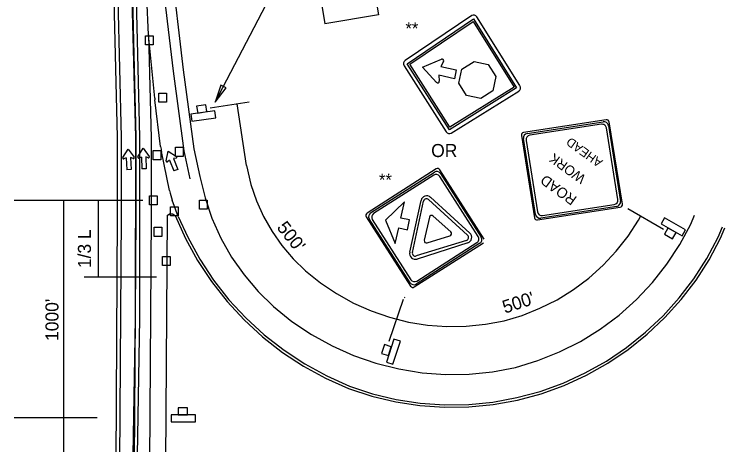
# Model space of a CAD drawing. Extents: x 612.5 to 619.9, y 600.8 to 610.9.
# Drawn here: x 615.256 to 618.528, y 604.113 to 606.093 of the extents above; entities that cross this region are included whole.
import ezdxf

# ---------------------------------------------------------------- set-up
doc = ezdxf.new("R2010")
doc.units = 0
for name, color, linetype in [('DETL-DIMS', 7, 'Continuous'), ('DETL-LINE', 7, 'Continuous'), ('DETL-NOTE', 7, 'Continuous'), ('USER-BORD', 7, 'Continuous')]:
    doc.layers.add(name, color=color, linetype=linetype)

# ---------------------------------------------------------------- blocks, each defined once
blk = doc.blocks.new('SIGN14')
at = {"layer": 'USER-BORD'}
for points in [[(-0.0134, 0.0182), (0.011, 0.0189), (0.011, 0.0371), (-0.0134, 0.0371)], [(-0.0314, 0.0182), (-0.0314, 0), (0.032, 0), (0.032, 0.0182)]]:
    blk.add_lwpolyline(points, close=True, dxfattribs=at)

msp = doc.modelspace()

# ---------------------------------------------------------------- linework, layer by layer
at = {"layer": 'DETL-DIMS'}
for p, q in [((616.1815, 605.6878), (616.5998, 606.491)), ((616.158, 605.6621), (616.3376, 605.6893)), ((616.3254, 605.3974), (616.2824, 605.6809)), ((615.8484, 605.2358), (615.2559, 605.2358)), ((615.485, 602.8086), (615.485, 605.2358)), ((615.6422, 605.2358), (615.6422, 604.8833)), ((618.2463, 605.1021), (618.0817, 605.1972)), ((615.9113, 604.8833), (615.5777, 604.8833)), ((616.9829, 604.5886), (617.0491, 604.7818)), ((615.6377, 604.2368), (615.2559, 604.2368))]:
    msp.add_line(p, q, dxfattribs=at)
msp.add_lwpolyline([(616.2314, 605.7535), (616.2074, 605.7661), (616.1815, 605.6878)], close=True, dxfattribs=at)
msp.add_lwpolyline([(616.3254, 605.3974), (616.3462, 605.3101), (616.3717, 605.2351), (616.4044, 605.1627), (616.4435, 605.0936), (616.489, 605.0284), (616.54, 604.968), (616.5966, 604.9129), (616.6656, 604.8574), (616.7397, 604.8076), (616.818, 604.7643), (616.8997, 604.728), (616.9843, 604.6989), (617.0712, 604.6771), (617.1593, 604.663), (617.2485, 604.6564), (617.3379, 604.6576), (617.4269, 604.6666), (617.5128, 604.6827), (617.595, 604.7075), (617.6771, 604.7404), (617.7558, 604.78), (617.8308, 604.8266), (617.9016, 604.8795), (617.9674, 604.9383), (618.0279, 605.0026), (618.0826, 605.072), (618.1311, 605.1459), (618.1404, 605.1632)], dxfattribs=at)
at = {"layer": 'DETL-LINE'}
for p, q in [((616.8941, 606.327), (616.933, 606.0896)), ((616.6468, 606.2864), (616.6857, 606.049)), ((615.8748, 605.9976), (615.8657, 606.181)), ((616.933, 606.0896), (616.6857, 606.049)), ((615.9032, 605.7068), (615.8748, 605.9976)), ((617.1358, 605.8489), (617.2232, 605.886)), ((617.2325, 605.876), (617.221, 605.8517)), ((617.3176, 605.8401), (617.374, 605.8761)), ((617.374, 605.8761), (617.4382, 605.862)), ((617.2011, 605.7795), (617.1358, 605.8489)), ((617.221, 605.8517), (617.2918, 605.8374)), ((617.2918, 605.8374), (617.2827, 605.7958)), ((617.3033, 605.7754), (617.3176, 605.8401)), ((617.4382, 605.862), (617.4743, 605.806)), ((617.2828, 605.7962), (617.2118, 605.8119)), ((617.2118, 605.8119), (617.2129, 605.7852)), ((617.4743, 605.806), (617.4603, 605.7404)), ((617.2011, 605.7795), (617.2011, 605.7795)), ((617.3394, 605.7194), (617.3033, 605.7754)), ((617.4603, 605.7404), (617.4041, 605.7052)), ((617.4041, 605.7052), (617.3394, 605.7194)), ((615.9303, 605.4846), (615.904, 605.6997)), ((617.9825, 605.6072), (617.6016, 605.5486)), ((617.6182, 605.5444), (617.9684, 605.5982)), ((617.9599, 605.5866), (617.6299, 605.5358)), ((617.9919, 605.5812), (618.0476, 605.2322)), ((618.0566, 605.2186), (617.9962, 605.5973)), ((618.0359, 605.2407), (617.9834, 605.5696)), ((617.5917, 605.5351), (617.6522, 605.1564)), ((617.6569, 605.172), (617.6011, 605.5211)), ((617.6129, 605.5126), (617.6655, 605.1837)), ((615.756, 605.4338), (615.7804, 605.4728)), ((615.7804, 605.4728), (615.8078, 605.4359)), ((615.8256, 605.437), (615.85, 605.476)), ((615.85, 605.476), (615.8774, 605.4391)), ((615.9711, 605.2814), (615.9342, 605.4607)), ((615.9551, 605.4182), (615.9646, 605.4632)), ((615.9646, 605.4632), (616.003, 605.4379)), ((615.772, 605.4321), (615.7607, 605.4278)), ((615.772, 605.4321), (615.7746, 605.3778)), ((615.8038, 605.4297), (615.792, 605.4331)), ((615.792, 605.4331), (615.7944, 605.3784)), ((615.8417, 605.4353), (615.8302, 605.431)), ((615.8417, 605.4353), (615.8442, 605.381)), ((615.8734, 605.433), (615.8616, 605.4362)), ((615.8616, 605.4362), (615.8638, 605.3817)), ((615.9707, 605.4221), (615.9614, 605.4142)), ((615.9707, 605.4221), (615.9916, 605.372)), ((616.0014, 605.4308), (615.9891, 605.4297)), ((615.9891, 605.4297), (616.0098, 605.3794)), ((615.7944, 605.3784), (615.7746, 605.3778)), ((615.8638, 605.3817), (615.8442, 605.381)), ((616.0098, 605.3794), (615.9916, 605.372)), ((617.1996, 605.381), (616.8809, 605.1775)), ((617.4198, 605.058), (617.2159, 605.3775)), ((616.8971, 605.1794), (617.1908, 605.367)), ((617.1877, 605.3531), (616.911, 605.1764)), ((617.3923, 605.0702), (617.2154, 605.347)), ((617.2185, 605.3609), (617.4061, 605.0672)), ((617.3542, 605.0861), (617.1732, 605.2507)), ((616.0114, 605.1627), (615.9835, 605.2381)), ((616.966, 605.1456), (617.0533, 605.23)), ((617.077, 604.9978), (617.1296, 605.2368)), ((617.0893, 604.9974), (617.1414, 605.2334)), ((617.1643, 605.2406), (617.3439, 605.0763)), ((617.6889, 605.1666), (618.0189, 605.2175)), ((617.6655, 605.1837), (617.6655, 605.1837)), ((617.6658, 605.1465), (618.0468, 605.2051)), ((618.0306, 605.209), (617.6803, 605.1551)), ((615.7303, 605.1667), (615.713, 602.4075)), ((615.7481, 605.1667), (615.7308, 602.4075)), ((615.8154, 605.1666), (615.7981, 602.4075)), ((615.8862, 605.1665), (615.8689, 602.4074)), ((615.9597, 605.1665), (615.9424, 602.4073)), ((616.8774, 605.1613), (617.0814, 604.8418)), ((617.0786, 604.8579), (616.891, 605.1516)), ((616.9048, 605.1485), (617.0816, 604.8718)), ((616.911, 605.1764), (616.9109, 605.1763)), ((616.966, 605.1456), (617.0108, 605.0382)), ((617.1677, 605.1591), (617.1444, 605.0534)), ((617.1677, 605.1592), (617.1677, 605.1591)), ((617.2661, 605.0915), (617.1849, 605.1646)), ((616.9838, 605.1078), (616.9838, 605.1078)), ((617.3386, 605.0528), (617.107, 604.9811)), ((617.1577, 605.0412), (617.2622, 605.0738)), ((617.0976, 604.8383), (617.4163, 605.0419)), ((617.4, 605.0394), (617.1063, 604.8518)), ((617.1094, 604.8657), (617.3862, 605.0425)), ((617.3444, 605.0414), (617.1108, 604.967))]:
    msp.add_line(p, q, dxfattribs=at)
for points in [[(615.743, 602.4107), (615.7794, 602.9085), (615.8185, 603.7952), (615.8337, 604.693), (615.8344, 605.528), (615.8187, 606.1632), (615.7799, 607.0362)], [(615.6811, 606.9197), (615.715, 606.1596), (615.7306, 605.5268), (615.7303, 605.1667)], [(615.6989, 606.9205), (615.7327, 606.1602), (615.7484, 605.5269), (615.7481, 605.1667)], [(615.7641, 606.9234), (615.798, 606.1625), (615.8137, 605.5277), (615.813, 604.6932), (615.7977, 603.7958), (615.7587, 602.9098), (615.7222, 602.4111)], [(615.7662, 606.9235), (615.8, 606.1626), (615.8157, 605.5277), (615.8154, 605.1666)], [(615.8847, 606.94), (615.9293, 606.3182), (615.9874, 605.8308), (616.0364, 605.4649), (616.065, 605.3359)], [(615.932, 606.9434), (615.9765, 606.3227), (616.0345, 605.8368), (616.0832, 605.4732), (616.1113, 605.3462)], [(615.932, 606.9434), (615.9765, 606.3227), (616.0345, 605.8368), (616.0832, 605.4732), (616.1113, 605.3462)], [(615.932, 606.9434), (615.9765, 606.3227), (616.0345, 605.8368), (616.0832, 605.4732), (616.1113, 605.3462)], [(615.932, 606.9434), (615.9765, 606.3227), (616.0345, 605.8368), (616.0832, 605.4732), (616.1113, 605.3462)], [(617.3626, 606.0866), (617.0562, 605.8797)], [(617.0662, 605.8652), (617.3716, 606.0709)], [(617.3716, 606.0709), (617.5696, 605.7546)], [(617.5842, 605.7646), (617.386, 606.0805)], [(617.0772, 605.8628), (617.3693, 606.0591)], [(617.3693, 606.0591), (617.5583, 605.7571)], [(615.8748, 605.9976), (615.8865, 605.5231), (615.8862, 605.1665)], [(617.2603, 605.5606), (617.0662, 605.8652)], [(617.0513, 605.8556), (617.2444, 605.5518)], [(617.2622, 605.573), (617.0772, 605.8628)], [(617.5696, 605.7546), (617.2603, 605.5606)], [(617.5583, 605.7571), (617.2622, 605.573)], [(617.2685, 605.5457), (617.5791, 605.7393)], [(616.1113, 605.3462), (616.1345, 605.249), (616.1667, 605.1542), (616.2078, 605.063), (616.257, 604.9761), (616.3143, 604.894), (616.3788, 604.8178), (616.4504, 604.748), (616.5349, 604.68), (616.625, 604.6195), (616.72, 604.567), (616.819, 604.523), (616.9215, 604.4877), (617.0269, 604.4612), (617.1338, 604.4441), (617.2419, 604.4362), (617.3504, 604.4376), (617.4583, 604.4485), (617.565, 604.4686), (617.6678, 604.4996), (617.7677, 604.5395), (617.8636, 604.5879), (617.955, 604.6446), (618.041, 604.7089), (618.1212, 604.7805), (618.1949, 604.8588), (618.2614, 604.9432), (618.3204, 605.0331), (618.3712, 605.1277), (618.3891, 605.1692)], [(615.9597, 605.1665), (615.9708, 605.1752), (615.985, 605.1755), (615.9964, 605.1671), (616.0441, 605.0615), (616.1001, 604.96), (616.1642, 604.8634), (616.2358, 604.7723), (616.3146, 604.6873), (616.4, 604.6089), (616.4914, 604.5377), (616.5882, 604.4741), (616.6899, 604.4185), (616.7958, 604.3713), (616.903, 604.336), (617.0128, 604.3097), (617.1244, 604.2927), (617.237, 604.2849), (617.3499, 604.2865), (617.4622, 604.2975), (617.5733, 604.3177), (617.6823, 604.3471), (617.7885, 604.3854), (617.8911, 604.4323), (617.9896, 604.4877), (618.083, 604.5509), (618.171, 604.6217), (618.2527, 604.6979), (618.3277, 604.7807), (618.3956, 604.8694), (618.4558, 604.9636), (618.5079, 605.0624), (618.5282, 605.1102)], [(616.0114, 605.1627), (616.0547, 605.0668), (616.1103, 604.9662), (616.1738, 604.8704), (616.2449, 604.78), (616.323, 604.6957), (616.4076, 604.618), (616.4983, 604.5473), (616.5944, 604.4842), (616.6952, 604.4291), (616.8001, 604.3823), (616.9063, 604.3474), (617.0151, 604.3214), (617.1257, 604.3045), (617.2373, 604.2968), (617.3492, 604.2984), (617.4606, 604.3093), (617.5707, 604.3293), (617.6787, 604.3584), (617.784, 604.3964), (617.8858, 604.4429), (617.9833, 604.4978), (618.076, 604.5605), (618.1632, 604.6307), (618.2442, 604.7063), (618.3186, 604.7883), (618.3859, 604.8762), (618.4455, 604.9695), (618.4971, 605.0675), (618.5172, 605.1148)], [(617.0524, 604.7914), (617.0551, 604.7904)]]:
    msp.add_lwpolyline(points, dxfattribs=at)
for points in [[(615.8965, 605.9518), (615.861, 605.9518), (615.861, 605.994), (615.8965, 605.994)], [(615.9575, 605.6878), (615.922, 605.6878), (615.922, 605.73), (615.9575, 605.73)], [(616.0344, 605.4384), (615.999, 605.4384), (615.999, 605.4806), (616.0344, 605.4806)], [(615.931, 605.4238), (615.8955, 605.4238), (615.8955, 605.466), (615.931, 605.466)], [(615.9138, 605.2156), (615.8783, 605.2156), (615.8783, 605.2578), (615.9138, 605.2578)], [(616.1445, 605.1957), (616.109, 605.1957), (616.109, 605.2379), (616.1445, 605.2379)], [(617.0666, 605.1017), (617.0765, 605.1465), (617.0368, 605.1553), (617.0533, 605.23), (616.966, 605.1456), (617.0108, 605.0382), (617.0267, 605.1105)], [(616.0106, 605.1652), (615.9751, 605.1652), (615.9751, 605.2074), (616.0106, 605.2074)], [(615.9363, 605.071), (615.9008, 605.071), (615.9008, 605.1132), (615.9363, 605.1132)], [(615.9748, 604.937), (615.9393, 604.937), (615.9393, 604.9792), (615.9748, 604.9792)]]:
    msp.add_lwpolyline(points, close=True, dxfattribs=at)
for centre, radius, start, end in [((616.1985, 605.7357), 0.2966, 185.5888, 186.9597), ((616.2247, 605.5205), 0.2966, 186.9597, 191.6264), ((615.7594, 605.4316), 0.00391, 148.1267, 290.387), ((615.8048, 605.4335), 0.00391, 254.3871, 36.6474), ((615.829, 605.4348), 0.00391, 148.1267, 290.387), ((615.8744, 605.4367), 0.00391, 254.3871, 36.6474), ((615.9589, 605.4173), 0.00391, 168.1267, 310.387), ((616.001, 605.4346), 0.00391, 274.3871, 56.6474), ((616.2616, 605.3412), 0.2966, 191.6264, 200.3362)]:
    msp.add_arc(centre, radius, start, end, dxfattribs=at)
for centre, major_axis, ratio, start_param, end_param in [((617.3717, 606.0714), (-0.0171, 0.0038), 0.999922, 3.926991, 5.497787), ((617.0662, 605.8652), (-0.0171, 0.0038), 0.999922, 5.54537, 7.042948), ((617.2264, 605.8791), (-0.00713, 0.00157), 0.999922, 2.884299, 5.327729), ((617.2061, 605.7846), (-0.00713, 0.00157), 0.999922, 0.964393, 3.407823), ((617.57, 605.7546), (0.0171, -0.0038), 0.999922, 5.421015, 7.068583), ((617.9844, 605.5955), (-0.011, 0.0047), 0.993733, 3.70184, 5.272637), ((617.9631, 605.5665), (-0.0188, 0.0081), 0.993733, 3.70184, 5.272637), ((617.9716, 605.5781), (-0.0188, 0.0081), 0.993733, 3.70184, 5.272637), ((617.2597, 605.5612), (-0.0171, 0.0038), 0.999922, 0.785398, 2.312744), ((617.6035, 605.5369), (-0.011, 0.0047), 0.993733, 5.272637, 6.843433), ((617.6214, 605.5242), (-0.0188, 0.0081), 0.993733, 5.272637, 6.843433), ((617.6331, 605.5157), (-0.0188, 0.0081), 0.993733, 5.272637, 6.843433), ((617.206, 605.3711), (-0.0115, 0.0025), 0.999922, 3.926991, 5.497787), ((617.1985, 605.3361), (-0.0196, 0.0043), 0.999922, 3.926991, 5.497787), ((617.2016, 605.35), (-0.0196, 0.0043), 0.999922, 3.926991, 5.497787), ((617.1555, 605.2311), (-0.0258, 0.0057), 0.999922, 4.191063, 6.283185), ((617.1549, 605.2304), (-0.0136, 0.003), 0.999922, 4.18832, 6.283185), ((618.0157, 605.2376), (-0.0188, 0.0081), 0.993733, 2.131044, 3.70184), ((618.0274, 605.2291), (-0.0188, 0.0081), 0.993733, 2.131044, 3.70184), ((618.0448, 605.2168), (-0.011, 0.0047), 0.993733, 2.131044, 3.70184), ((616.9079, 605.1624), (-0.0196, 0.0043), 0.999922, 5.497787, 7.068583), ((617.6856, 605.1868), (-0.0188, 0.0081), 0.993733, 0.560248, 2.131044), ((616.8873, 605.1676), (-0.0115, 0.0025), 0.999922, 5.497787, 7.068583), ((616.9218, 605.1593), (-0.0196, 0.0043), 0.999922, 5.497787, 7.068583), ((617.178, 605.1569), (-0.0102, 0.0023), 0.999922, 4.195513, 6.283185), ((617.6639, 605.1582), (-0.011, 0.0047), 0.993733, 0.560248, 2.131044), ((617.6771, 605.1752), (-0.0188, 0.0081), 0.993733, 0.560248, 2.131044), ((617.2591, 605.0837), (-0.0102, 0.0023), 0.999922, 2.089942, 4.195513), ((617.3364, 605.0665), (-0.0258, 0.0057), 0.999922, 2.096108, 4.191063), ((617.1546, 605.0512), (-0.0102, 0.0023), 0.999922, 0, 2.089942), ((617.3346, 605.066), (-0.0136, 0.003), 0.999922, 2.087614, 4.18832), ((617.3753, 605.0594), (-0.0196, 0.0043), 0.999922, 2.356194, 3.926991), ((617.3892, 605.0563), (-0.0196, 0.0043), 0.999922, 2.356194, 3.926991), ((617.1028, 604.9921), (-0.0258, 0.0057), 0.999922, 0, 2.096108), ((617.1029, 604.9944), (-0.0136, 0.003), 0.999922, 0, 2.087614), ((617.0955, 604.8687), (-0.0196, 0.0043), 0.999922, 0.785398, 2.356194), ((617.0985, 604.8826), (-0.0196, 0.0043), 0.999922, 0.785398, 2.356194), ((617.0913, 604.8482), (-0.0115, 0.0025), 0.999922, 0.785398, 2.356194)]:
    msp.add_ellipse(centre, major_axis=major_axis, ratio=ratio, start_param=start_param, end_param=end_param, dxfattribs=at)

# ---------------------------------------------------------------- block references
for p, xscale, yscale, rotation in [((616.1286, 605.609), 1.7600000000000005, 1.76, 8.169929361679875), ((618.2992, 605.129), 1.76, 1.76, 150.58985740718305), ((617.0171, 604.5352), 1.7600000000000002, 1.7600000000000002, 72.10824108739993)]:
    msp.add_blockref('SIGN14', p, dxfattribs=dict(at, xscale=xscale, yscale=yscale, rotation=rotation))
at = {"layer": 'DETL-LINE', "xscale": 1.7600000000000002, "yscale": 1.7600000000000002}
msp.add_blockref('SIGN14', (616.0345, 604.2176), dxfattribs=at)

# ---------------------------------------------------------------- texts
at = {"layer": 'DETL-LINE'}
for s, height, p in [('AHEAD', 0.04079, (617.9693, 605.419)), ('WORK', 0.04479, (617.8918, 605.3462)), ('ROAD', 0.04764, (617.8506, 605.2495))]:
    msp.add_text(s, height=height, rotation=143.9897, dxfattribs=at).set_placement(p)
at = {"layer": 'DETL-NOTE'}
for s, height, p in [('**', 0.057, (617.0576, 605.9988)), ('OR', 0.06, (617.1761, 605.4359)), ('**', 0.057, (616.9357, 605.3026))]:
    msp.add_text(s, height=height, dxfattribs=at).set_placement(p)
for s, rotation, p in [("500'", 308.5893, (616.4622, 605.1107)), ('1/3 L', 90, (615.6092, 604.925)), ("500'", 18.0143, (617.5156, 604.7156)), ("1000'", 90, (615.4597, 604.5902))]:
    msp.add_text(s, height=0.06, rotation=rotation, dxfattribs=at).set_placement(p)

doc.saveas('drawing.dxf')
